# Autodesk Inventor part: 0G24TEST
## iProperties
Created: 2007-01
Description: Blech lt. Tab.
Document SubType Name: Blech
Designer: R.Pilz
Part Number: 0G24TEST
ArtNrPrefix: HZ
ArtNrAuto: 0
EDVNum=ArtNr: 0
Bez=Mat: 0
ArtNrBackSpace: 0
EDVNrBackSpace: 0
EDVNrAuto: 0
ProdGruppe: ÜKWW
ProdBezeichnung: Blende
ArtNr: lt. Tab.
EDVNr: lt. Tab
KommaZuschnitt: 0
Zeichnungsnummer: 0G24 TE ST
Konstrukteur: R.Pilz
Erstellungsdatum: 10.01.2007
GesGewicht: 0,1kg
Material: Standard
Title: Platte
Author: R.Pilz
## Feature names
1. Abgeleiteter Körper1 [Tagging]
